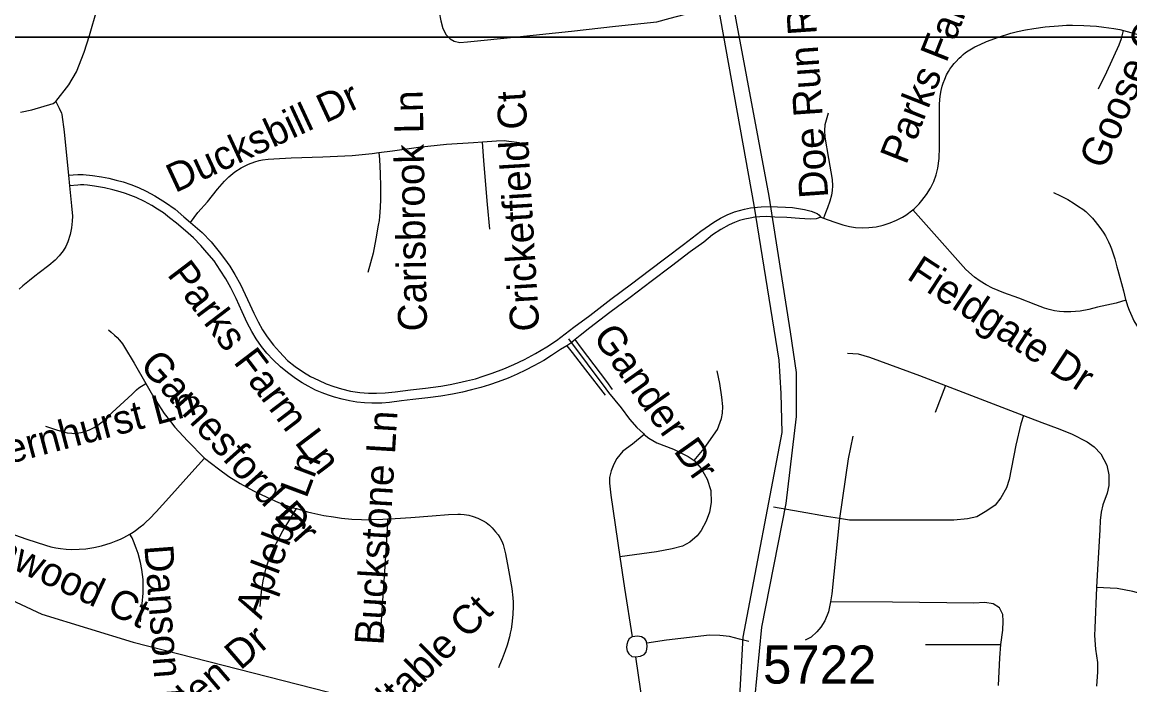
# Model space of a CAD drawing. Extents: x 1383679 to 1536984, y 460658 to 651027.
# Drawn here: x 1456433 to 1460069, y 475190 to 477365 of the extents above; entities that cross this region are included whole.
import ezdxf

# ---------------------------------------------------------------- set-up
doc = ezdxf.new("R2010")
doc.units = 0
for name, color, linetype in [('Exist Road Non-System Type 51', 7, 'Continuous'), ('Exist Road Non-System Type 51 Label', 7, 'Continuous'), ('Exist Road Secondary Type 51 Attributed', 7, 'Continuous'), ('Exist Road Secondary Type 51 Divided Attributed', 7, 'Continuous'), ('Exist Road Secondary Type 51 Number Label', 7, 'Continuous'), ('Exist Utilities Electrical Transmission Line', 7, 'Continuous'), ('Map Preparation Inset Cut Line', 7, 'Continuous')]:
    doc.layers.add(name, color=color, linetype=linetype)

msp = doc.modelspace()

# ---------------------------------------------------------------- linework, layer by layer
at = {"layer": 'Exist Road Non-System Type 51'}
for p, q in [((1456584.9, 476862.5), (1456588.5, 476827.7)), ((1459054.5, 476725.2), (1459063, 476722.4)), ((1459463.6, 476172.8), (1459429.6, 476083.9)), ((1459463.6, 476172.8), (1459720.1, 476074)), ((1459398, 475322.6), (1459645.4, 475323.2))]:
    msp.add_line(p, q, dxfattribs=at)
for points in [[(1457696.4, 477548.9), (1457721.9, 477541.8), (1457745.6, 477535.2), (1457767.6, 477524), (1457784.2, 477510.3), (1457792.6, 477496.1), (1457796.8, 477480.6), (1457798.5, 477452.7), (1457799.8, 477422.4), (1457801.5, 477397.4), (1457806.9, 477369.5), (1457813.4, 477344.6), (1457824.1, 477323.2), (1457837.8, 477310.1), (1457851.2, 477302.5), (1457869.2, 477298.8), (1457894.8, 477300.6), (1458057.6, 477317.2), (1458235.9, 477335.7), (1458380.1, 477352.2), (1458515.6, 477366.4), (1458559.6, 477378.7), (1458606.1, 477389.7), (1458624.4, 477398.2)], [(1459637.4, 477316), (1459678.3, 477328.6), (1459699.5, 477334.2), (1459725.7, 477339.6), (1459754, 477344.2), (1459790.9, 477349.2), (1459834.1, 477353.4), (1459861.3, 477354.8), (1459880.9, 477355.1), (1459917.3, 477354.5), (1459959.5, 477351.6), (1459983.5, 477349.1), (1460016.5, 477344.4), (1460035.4, 477341), (1460048.1, 477338)], [(1459966.3, 477146.8), (1459993, 477202), (1460033.9, 477290.6), (1460041.5, 477311.7), (1460048.1, 477338)], [(1460048.1, 477338), (1460147.2, 477310.3), (1460200.9, 477290.3), (1460427.4, 477206)], [(1459356.5, 476749.5), (1459362.2, 476753.9), (1459377.5, 476769.4), (1459385.9, 476779.8), (1459401.2, 476799.8), (1459414, 476820.8), (1459424.9, 476842), (1459433.2, 476863.8), (1459438.7, 476885.9), (1459442.9, 476918), (1459444.1, 476955.2), (1459444.3, 477026.3), (1459444.3, 477066), (1459444.3, 477093.6), (1459445, 477112.7), (1459446.9, 477129.2), (1459449.1, 477141.1), (1459452.6, 477154.5), (1459455.7, 477164.4), (1459460.9, 477177.9), (1459467.3, 477192.5), (1459473.3, 477203.1), (1459478.1, 477210.6), (1459484.3, 477219.4), (1459492.4, 477229.2), (1459497.1, 477234.9), (1459508.5, 477247.2), (1459514.7, 477252.9), (1459522, 477259), (1459529.3, 477265.2), (1459537.8, 477271.3), (1459548.6, 477277.8), (1459559.9, 477284.3), (1459577, 477292.3), (1459598.3, 477301.2), (1459637.4, 477316)], [(1456542.8, 477104.2), (1456554.3, 477082.8), (1456561.8, 477066), (1456563.1, 477062), (1456571, 477004.9), (1456579.4, 476916.4), (1456584.9, 476862.5)], [(1459078.2, 477066), (1459067.7, 477028.5), (1459066.4, 477009.7), (1459068, 476987.4), (1459079.7, 476917.3), (1459091.8, 476849.1), (1459092.9, 476827.9), (1459092, 476812.4), (1459089.1, 476797), (1459083.9, 476777.7), (1459076.6, 476756.3), (1459069.7, 476739.6), (1459063, 476722.4)], [(1457603.7, 476937), (1457648.8, 476943.1), (1457734, 476955), (1457825.3, 476964.2), (1457914.1, 476970.7), (1457944, 476972.7)], [(1457944, 476972.7), (1457990.1, 476975.6), (1458014.6, 476976.3), (1458029.8, 476975.1), (1458065.2, 476970.2)], [(1457968.1, 476685.7), (1457960.4, 476766.5), (1457948.7, 476909.9), (1457944, 476972.7)], [(1456985.6, 476707.2), (1457009.8, 476740.7), (1457041.3, 476776), (1457074.4, 476816.6), (1457097.2, 476843.1), (1457111, 476857.3), (1457131, 476873.7), (1457151.9, 476887.4), (1457175.5, 476898.9), (1457196, 476906.7), (1457210.4, 476910.7), (1457221.7, 476913.1), (1457240.3, 476915.8), (1457258.5, 476917), (1457315.9, 476919.5), (1457420.1, 476923.4), (1457516.1, 476928), (1457581.9, 476934), (1457603.7, 476937)], [(1457603.7, 476937), (1457605.7, 476914.8), (1457607.7, 476868), (1457609, 476824.8), (1457608.8, 476784.6), (1457608.2, 476756.6), (1457606, 476727.1), (1457604.5, 476714.7), (1457601.8, 476698.6), (1457593.8, 476654.2), (1457584.5, 476606.7), (1457567.5, 476543.4)], [(1456584.9, 476862.5), (1456615.6, 476865.2), (1456632.6, 476864.7), (1456663.3, 476862), (1456692.9, 476857.5), (1456717.6, 476853.2), (1456741.6, 476847.1), (1456764.1, 476841.1), (1456789.5, 476832.1), (1456814.4, 476822.5), (1456839.4, 476810.8), (1456868.8, 476795.4), (1456902.9, 476773.8), (1456935, 476751), (1456963.2, 476726.8), (1456985.6, 476707.2)], [(1456588.5, 476827.7), (1456595.1, 476762.9), (1456597.6, 476728), (1456597.2, 476712), (1456594.8, 476690.6), (1456590.4, 476668.2), (1456583.1, 476644.6), (1456575.6, 476628.5), (1456567.1, 476614.9), (1456554.7, 476598.6), (1456541.1, 476584.4), (1456520.7, 476566.1), (1456488.6, 476542.1), (1456474.4, 476531.5), (1456457.3, 476517.8), (1456435.5, 476499.8), (1456423.3, 476489.3)], [(1458220.5, 476303.3), (1458200.1, 476290.4), (1458170.7, 476270.7), (1458145.1, 476255.1), (1458112.5, 476237.6), (1458085.5, 476223.5), (1458057.8, 476210.1), (1458027.9, 476197.3), (1457995.5, 476185.3), (1457967.2, 476175.2), (1457938.1, 476166.2), (1457907.6, 476158.2), (1457877.8, 476150.7), (1457845, 476144.1), (1457807.4, 476137.7), (1457764.6, 476132.6), (1457715, 476126.8), (1457678.3, 476122.2), (1457638.6, 476116.7), (1457613.7, 476115), (1457580.8, 476114.4), (1457556.5, 476115.9), (1457530.8, 476118.6), (1457506.9, 476122.3), (1457483.2, 476127.4), (1457458.5, 476134.3), (1457438, 476140.8), (1457417.6, 476148.4), (1457396, 476158), (1457371.2, 476170.1), (1457351.5, 476181.6), (1457330, 476196.1), (1457303.6, 476215.3), (1457281.1, 476234.1), (1457256.8, 476257.5), (1457236.4, 476278.7), (1457218.6, 476300.5), (1457200.9, 476326.4), (1457186.8, 476350), (1457171.8, 476378.7), (1457155.4, 476414.4), (1457135.4, 476458.1), (1457117.9, 476492.8), (1457101.8, 476522.4), (1457083.1, 476551.7), (1457062.5, 476581.7), (1457039.3, 476609.3), (1457018.8, 476632.7), (1456995.2, 476657.5), (1456969.4, 476680.8), (1456939.2, 476706), (1456916.6, 476723.4), (1456896.3, 476738.9), (1456877.4, 476751.5), (1456858.6, 476763), (1456834.3, 476776.2), (1456806.7, 476789.4), (1456771.5, 476803.1), (1456754, 476808.7), (1456730.2, 476815.4), (1456702.8, 476821.6), (1456669.8, 476827.2), (1456647.2, 476829.8), (1456635.5, 476830.8), (1456624.8, 476831), (1456615.7, 476830.5), (1456588.5, 476827.7)], [(1459817.7, 476806.2), (1459840.6, 476795.2), (1459865.2, 476782.8), (1459886.1, 476770.3), (1459900.5, 476760.7), (1459914.1, 476751.4), (1459924, 476743.4), (1459933.1, 476735.3), (1459945.8, 476721.8), (1459955.2, 476711.2), (1459963, 476701.5), (1459973.7, 476687), (1459982.9, 476672.8), (1459988.8, 476663.4), (1459993.9, 476653.4), (1459998.9, 476644), (1460003.9, 476632.1), (1460008.5, 476620.8), (1460013, 476608.3), (1460019, 476588.4), (1460026.5, 476562.2), (1460029.8, 476550.9), (1460047.5, 476483.5), (1460054.8, 476455.2), (1460055.6, 476452.3)], [(1456985.6, 476707.2), (1457023.2, 476674.4), (1457053.3, 476644.2), (1457079.7, 476611.3), (1457097.4, 476588.6), (1457113.9, 476564.5), (1457131.1, 476537.5), (1457149.3, 476504.5), (1457165, 476471.6), (1457180.2, 476438.7), (1457193, 476410.2), (1457207.3, 476382.2), (1457221.7, 476355.9), (1457237.4, 476332.3), (1457257.3, 476305.3), (1457277.3, 476282.9), (1457304.2, 476255.1), (1457328.9, 476235.2), (1457356.3, 476216.5), (1457379.5, 476202.5), (1457405.1, 476189.8), (1457431, 476178.3), (1457455.8, 476169.4), (1457480.6, 476161.5), (1457510.1, 476154.7), (1457541.1, 476150.3), (1457570, 476148), (1457596.2, 476147.2), (1457623.8, 476148.5), (1457657.4, 476152.4), (1457707.9, 476158.6), (1457756.3, 476164.2), (1457807, 476171), (1457837.7, 476176.3), (1457863.3, 476181.2), (1457890.9, 476187.6), (1457920.5, 476195.1), (1457945.9, 476203), (1457975.6, 476213.2), (1458014.3, 476227.9), (1458046.5, 476241.4), (1458081.8, 476258.6), (1458118.2, 476278), (1458154.9, 476300.1), (1458186.2, 476320), (1458243.8, 476363.9), (1458296.1, 476402.3), (1458365.6, 476455.7), (1458432.4, 476506.4), (1458492.5, 476551.5), (1458545.5, 476591.3), (1458603.3, 476635.2), (1458660.7, 476678.9), (1458703.1, 476709.1), (1458724.7, 476722.3), (1458746.7, 476733.3), (1458771.3, 476743.1), (1458803.8, 476751.6), (1458823, 476755.4), (1458858.7, 476759.2), (1458889, 476759.9), (1458912.2, 476759), (1458938.8, 476758.1), (1458961.3, 476756.5), (1458981, 476753.9), (1459000.6, 476750.2), (1459022.7, 476744.4), (1459042.2, 476736.9), (1459048.3, 476732.7), (1459054.5, 476725.2)], [(1459063, 476722.4), (1459096.7, 476709.5), (1459126.2, 476700.1), (1459148.1, 476694.5), (1459167.7, 476691.4), (1459191.3, 476690.3), (1459211.9, 476691.4), (1459236.1, 476693.2), (1459258.7, 476698.7), (1459282.5, 476706.6), (1459303.3, 476715.8), (1459322.3, 476725.1), (1459333.1, 476731.8), (1459356.5, 476749.5)], [(1460055.6, 476452.3), (1460023.5, 476443.2), (1459962.9, 476429.3), (1459934.4, 476422.7), (1459905.5, 476416.9), (1459890.4, 476415.4), (1459875.3, 476414.2), (1459852.2, 476414.4), (1459837.3, 476415.4), (1459820.9, 476418), (1459803.9, 476421.8), (1459789, 476426.5), (1459760.4, 476437.2), (1459704.1, 476459), (1459654.9, 476477.4), (1459618, 476492.1), (1459597.3, 476502.7), (1459577, 476514.9), (1459558.6, 476527.9), (1459530.8, 476553.7), (1459417.4, 476680.4), (1459356.5, 476749.5)], [(1459054.5, 476725.2), (1459039, 476719.2), (1459019.6, 476718.6), (1458983.9, 476721.3), (1458942.6, 476724.1), (1458902.9, 476725.6), (1458875.1, 476727.4), (1458853.9, 476726.5), (1458837.3, 476724.8), (1458821.9, 476722.3), (1458804.9, 476718.4), (1458787.6, 476713.7), (1458770.6, 476707.5), (1458753.4, 476699.6), (1458725.8, 476684.6), (1458699.1, 476666.9), (1458669.8, 476643.6), (1458625.7, 476610.9), (1458564.3, 476564.8), (1458497.8, 476514), (1458428.6, 476461.7), (1458362.3, 476411.8), (1458295.9, 476361.9), (1458263.9, 476336.5), (1458247.9, 476323.4)], [(1460055.6, 476452.3), (1460060.9, 476434.2), (1460066.7, 476419.7), (1460074.8, 476400.6), (1460082.2, 476385.5), (1460090.5, 476370.8), (1460108.8, 476344.9), (1460128.3, 476322.7), (1460151, 476300.6), (1460179.1, 476279.1), (1460206.6, 476261.9), (1460237.1, 476248), (1460271.7, 476235), (1460320.8, 476221.1), (1460394.2, 476200.3), (1460437, 476190.9)], [(1456715.8, 476355.7), (1456725.3, 476348.3), (1456736.1, 476338.4), (1456744.8, 476330.1), (1456752.6, 476321.3), (1456761.7, 476309.9), (1456769, 476298.8), (1456800.7, 476246), (1456838.6, 476179.7)], [(1458247.9, 476323.4), (1458233.6, 476311.6), (1458220.5, 476303.3)], [(1458226.5, 476325.8), (1458348.4, 476161.9), (1458357.4, 476149.8), (1458398.5, 476100), (1458426.2, 476062.7), (1458450.4, 476034.9), (1458472.1, 476015.6), (1458474.6, 476011.5)], [(1458370.6, 476160.2), (1458351.5, 476185.4), (1458269.2, 476294.8), (1458247.9, 476323.4)], [(1458220.5, 476303.3), (1458237.9, 476281.1), (1458282, 476223.8), (1458346.1, 476140.9)], [(1459142.1, 476279.2), (1459176.9, 476276.7), (1459214.6, 476266.3), (1459378.2, 476205.5), (1459463.6, 476172.8)], [(1458639.1, 475927.2), (1458671, 475965.9), (1458715.6, 476028.9), (1458728.2, 476064.1), (1458731.8, 476081.6), (1458732.9, 476103.8), (1458729.4, 476134.2), (1458722.9, 476179.7), (1458714.5, 476220.7)], [(1456509.2, 476039.7), (1456548.7, 476026.3), (1456568.4, 476020.3), (1456581, 476017.8), (1456596.2, 476015.9), (1456601.6, 476015.6), (1456609.4, 476015.9), (1456618.7, 476017.3), (1456626.6, 476018.9), (1456638.4, 476022.2), (1456653.3, 476027.3), (1456662.2, 476031.3), (1456669.2, 476035), (1456681.4, 476042.6), (1456691.4, 476050.2), (1456698.2, 476055.9), (1456728.1, 476084), (1456793.5, 476144.6), (1456808.2, 476158.2), (1456816.2, 476164.6), (1456838.6, 476179.7)], [(1456838.6, 476179.7), (1456860.8, 476140.8), (1456878.8, 476111.3), (1456898.8, 476081.4), (1456919.2, 476054.8), (1456934.3, 476036.3), (1456976, 475990.7), (1457031.7, 475934.3)], [(1459720.1, 476074), (1459710.6, 476046.6), (1459694.6, 475976.7), (1459672.9, 475864.2), (1459663.4, 475836.8), (1459645.5, 475804.7), (1459626.6, 475780.1), (1459599.1, 475761.2), (1459566.1, 475742.3), (1459535.9, 475734.8), (1459490.5, 475730.9), (1459190, 475730.9), (1459148.4, 475730.9), (1459116.1, 475736.6)], [(1459720.1, 476074), (1459779.5, 476051.4), (1459830.6, 476032.5), (1459877.4, 476013.8), (1459928.9, 475988.1), (1459951.1, 475971.8), (1459973.4, 475948.3), (1459993, 475911.2), (1459999.2, 475879.8), (1459999.2, 475845), (1459994.8, 475820), (1459980.5, 475781.6), (1459975.1, 475757.5), (1459971.5, 475729.8), (1459970.6, 475699.4), (1459960.9, 475550.2), (1459959.1, 475509.8)], [(1458474.6, 476011.5), (1458435.9, 475980.7), (1458404.6, 475957.8), (1458385.2, 475933.6), (1458374.4, 475914.3), (1458365.9, 475892.6), (1458361.1, 475870.9), (1458361.1, 475852.8), (1458364.8, 475813), (1458394.4, 475610.1)], [(1458474.6, 476011.5), (1458489.8, 475999.8), (1458516.6, 475984.6), (1458570.4, 475963.5), (1458618.4, 475940.2), (1458639.1, 475927.2)], [(1459159.6, 476006.8), (1459144.2, 475932.2), (1459116.1, 475736.6)], [(1456786.3, 475685), (1456786.5, 475685.1), (1456796.6, 475691.4), (1456804.6, 475697), (1456820.2, 475708.7), (1456831.8, 475718.1), (1456840.3, 475725.4), (1456850.5, 475735.2), (1456872.9, 475758), (1456914.7, 475804.2), (1456990.2, 475888.6), (1457031.7, 475934.3)], [(1457031.7, 475934.3), (1457077.1, 475899.1), (1457111.5, 475874.6), (1457148.6, 475851.2), (1457191.7, 475827.5), (1457235.6, 475805.9), (1457274.6, 475789.1), (1457318.1, 475772.8), (1457332.8, 475768.7)], [(1458639.1, 475927.2), (1458661.6, 475900.4), (1458681.5, 475865.3), (1458693.1, 475827.9), (1458694.4, 475789.3), (1458688.5, 475756.6), (1458678, 475727.4), (1458661.6, 475697), (1458648.1, 475679.2), (1458624.1, 475658.7), (1458599.9, 475645.3), (1458566.1, 475636.9), (1458515.5, 475627.2), (1458394.4, 475610.1)], [(1457213.5, 475448.1), (1457218.1, 475496), (1457223.9, 475532.2), (1457234, 475574), (1457241.7, 475597.3), (1457248.6, 475616.4), (1457258.8, 475638.5), (1457267.4, 475657), (1457288.8, 475696), (1457310.4, 475730.4), (1457332.8, 475768.7)], [(1457332.8, 475768.7), (1457369.1, 475758.7), (1457383.8, 475755), (1457422.9, 475746.6), (1457454.2, 475741.3), (1457480.5, 475737.8), (1457514.4, 475734.6), (1457546.5, 475732.9), (1457571.8, 475732.5), (1457578.1, 475732.7), (1457616.5, 475733.8), (1457632.9, 475734.8)], [(1459116.1, 475736.6), (1459072.8, 475743.2), (1458986.8, 475758.3), (1458899.4, 475773.4)], [(1456235.7, 475756.1), (1456261.9, 475741.2), (1456304.2, 475722.1), (1456367.1, 475697.5), (1456448.1, 475668.7), (1456509.6, 475648.3), (1456527.1, 475643.6), (1456543.8, 475639.9), (1456558.8, 475637.6), (1456577.5, 475635.6), (1456594.4, 475634.9), (1456620.2, 475635.5), (1456642.3, 475636.9), (1456668.1, 475641.1), (1456693.7, 475646.8), (1456725.2, 475656.5), (1456741.4, 475662.8), (1456755.3, 475668.9), (1456766.8, 475674.1), (1456776.2, 475679.2), (1456786.3, 475685)], [(1457609, 475348.2), (1457613.7, 475417.5), (1457624, 475578.4), (1457632.6, 475719.2), (1457632.9, 475734.8)], [(1457632.9, 475734.8), (1457657.4, 475736.2), (1457708.7, 475739.9), (1457778.4, 475745.2), (1457832.2, 475749), (1457863.1, 475750.8), (1457871.7, 475750.7), (1457883.4, 475749.9), (1457898.8, 475747.4), (1457913.4, 475743.2), (1457928.2, 475737.7), (1457946.3, 475729.1), (1457955.5, 475723.4), (1457966.9, 475714.8), (1457975.8, 475705.8), (1457986.7, 475693.1), (1457994.8, 475682.8), (1458001.2, 475673.5), (1458006.8, 475662.4), (1458011.6, 475650.8), (1458015.2, 475638.4), (1458019.6, 475620.1), (1458028.4, 475573.5), (1458039.7, 475506.9), (1458043.6, 475475.5), (1458044.3, 475461.6), (1458044.7, 475449.2), (1458043.4, 475421.4), (1458039.9, 475389.9), (1458037.6, 475373.4), (1458035.1, 475359.6), (1458032.3, 475348.3), (1458024.8, 475321), (1458018.2, 475302.4), (1458008.2, 475275.7), (1457999.9, 475255.1), (1457995.9, 475246)], [(1459116.1, 475736.6), (1459090.5, 475489), (1459085.6, 475462.7)], [(1456821.7, 475397.6), (1456827, 475455.9), (1456829.7, 475491), (1456830.3, 475516.1), (1456829.7, 475536.6), (1456828.2, 475552.5), (1456825.7, 475569.3), (1456821.1, 475592.2), (1456813.2, 475621.2), (1456807.4, 475639.3), (1456798.4, 475662.5), (1456793.7, 475672.7), (1456786.3, 475685)], [(1458394.4, 475610.1), (1458409.4, 475507.9), (1458435.6, 475348.2)], [(1459959.1, 475509.8), (1459953.6, 475376), (1459952.8, 475351.9), (1459956.4, 475308.1), (1459962.6, 475264.3), (1459962.6, 475233.1), (1459959.2, 475186.1)], [(1460624.9, 475267.2), (1460612.4, 475284.3), (1460577.6, 475329.1), (1460539.4, 475358.9), (1460503, 475378.8), (1460428.4, 475400.4), (1460078.6, 475496.6), (1460027.1, 475506.5), (1459959.1, 475509.8)], [(1459085.6, 475462.7), (1459080, 475429.8), (1459067, 475400.7), (1459054, 475380.2)], [(1459645.4, 475323.2), (1459652.2, 475369.7), (1459653.4, 475399.4), (1459652.2, 475421.2), (1459640.4, 475443.5), (1459620.6, 475455.8), (1459592.6, 475460.2), (1459556.8, 475459), (1459289.6, 475461.4), (1459085.6, 475462.7)], [(1459054, 475380.2), (1459041.6, 475364.8), (1459022.4, 475347.4), (1459003.1, 475336.8)], [(1458435.6, 475348.2), (1458425, 475341.9), (1458420.4, 475333.3), (1458417.6, 475323), (1458416.9, 475312.6), (1458418.6, 475300.8), (1458423.9, 475291.8), (1458434.1, 475284), (1458445.6, 475282.5)], [(1458483, 475327.2), (1458480.6, 475335.4), (1458476.9, 475341.8), (1458465.8, 475347.8), (1458452.1, 475349.8), (1458435.6, 475348.2)], [(1458818.1, 475333.2), (1458787.9, 475340.5), (1458754.1, 475348.9), (1458722.6, 475352.6), (1458688.8, 475353.8), (1458548.1, 475336.7), (1458483, 475327.2)], [(1458445.6, 475282.5), (1458462.4, 475284.5), (1458474.1, 475290.3), (1458480.6, 475297.9), (1458483, 475307.3), (1458483.8, 475316.9), (1458483, 475327.2)], [(1459637.9, 475188.2), (1459642.2, 475278.6), (1459645.4, 475323.2)], [(1458445.6, 475282.5), (1458469.6, 475117.2), (1458485.1, 475018.3)]]:
    msp.add_lwpolyline(points, dxfattribs=at)
at = {"layer": 'Exist Road Secondary Type 51 Attributed'}
msp.add_lwpolyline([(1456427.3, 477070.2), (1456464.2, 477077), (1456534.3, 477098.6), (1456542.8, 477104.2), (1456585.7, 477158.9), (1456611.4, 477202.6), (1456636.6, 477266.2), (1456653.7, 477321), (1456829.7, 477934.5), (1456869, 478083.4), (1456883.3, 478148.5), (1456909.6, 478279.4), (1456951.5, 478498.5), (1457079.3, 479143.2), (1457091.1, 479196.8), (1457099.8, 479243.5), (1457101.4, 479259), (1457091.2, 479364.1), (1457067.4, 479430.8), (1456494.2, 480699.2)], dxfattribs=at)
at = {"layer": 'Exist Road Secondary Type 51 Divided Attributed'}
for points in [[(1458837.8, 475143.5), (1458860.6, 475380), (1458940.2, 475785.1), (1458975, 476071.6), (1458974.4, 476215.4), (1458954.5, 476349.3), (1458884.4, 476793.7), (1458630.1, 478157.4), (1458544.7, 478502.2), (1458470.7, 478670.4), (1458422.3, 478781.5), (1458271.4, 479018.1), (1458100.5, 479226.1), (1457884.5, 479508.8), (1457764.8, 479708.1), (1457688, 479902.1), (1457668.3, 480076.8), (1457671.2, 480649.6), (1457683.3, 481012.4)], [(1457618.7, 480994.9), (1457614.2, 480886.1), (1457614.2, 480629.6), (1457614, 480244), (1457625.4, 479987.5), (1457645.3, 479865), (1457717.2, 479668.5), (1457799.1, 479528.7), (1457995.2, 479271.7), (1458223, 478995.3), (1458353.9, 478807.2), (1458442.2, 478630.5), (1458527.6, 478391.1), (1458613.1, 477994.2), (1458834.8, 476764.4), (1458916.6, 476255.7), (1458923.1, 476147), (1458926, 476018.8), (1458798.2, 475346.4), (1458786.6, 475132.1)]]:
    msp.add_lwpolyline(points, dxfattribs=at)
at = {"layer": 'Exist Utilities Electrical Transmission Line'}
msp.add_lwpolyline([(1453014.9, 477138.1), (1453821.9, 476745.3), (1454321.7, 476494.2), (1454964, 476178.3), (1455473.7, 475920.9), (1455981.2, 475667.6), (1456308.6, 475509.6), (1456496.9, 475421.9), (1456797.4, 475330.4), (1457486.6, 475153.9), (1458281.1, 474943.2), (1458957.9, 474758.9), (1459627.2, 474588.6), (1460274, 474406.7), (1460927.2, 474230.7), (1461607.9, 474042.3), (1462317, 473863.2)], dxfattribs=at)
at = {"layer": 'Map Preparation Inset Cut Line'}
for points in [[(1446195.4, 477316), (1480703, 477316), (1498974.3, 494868.2), (1521133.6, 516155.5), (1521133.6, 520758.2), (1458567.8, 520758.2), (1458567.8, 493672.2), (1446195.4, 493672.2), (1446195.4, 477316)], [(1437474.3, 477316), (1437474.3, 461213.3), (1475802.8, 461213.3), (1475802.8, 477316), (1437474.3, 477316)]]:
    msp.add_lwpolyline(points, dxfattribs=at)

# ---------------------------------------------------------------- texts
at = {"layer": 'Exist Road Non-System Type 51 Label'}
for s, rotation, p in [('Parks Farm Ln', 68.4908, (1459334.2, 476893.9)), ('Doe Run Rd', 94.0064, (1459079.2, 476790.1)), ('Goose Ct', 66.8976, (1459986.5, 476878.4)), ('Ducksbill Dr', 24.8776, (1456934.7, 476803.7)), ('Carisbrook Ln', 91.0627, (1457762.1, 476351.1)), ('Cricketfield Ct', 93.4121, (1458130.9, 476352.9)), ('Parks Farm Ln', 307.2228, (1456906.2, 476536.6)), ('Fieldgate Dr', 326.7355, (1459332.7, 476524.9)), ('Gander Dr', 305.3645, (1458303.2, 476332.6)), ('Gamesford Dr', 311.7076, (1456815.1, 476237)), ('Fernhurst Ln', 14.8392, (1456313.8, 475894.8)), ('Buckstone Ln', 86.5463, (1457618.5, 475319)), ('Apleby Ln', 69.4967, (1457217.3, 475402.6)), ('Charnwood Ct', 335.037, (1456084.8, 475717.4)), ('Danson Dr', 274.338, (1456833.5, 475646.9)), ('Roundtable Ct', 44.9373, (1457408.8, 474854.3)), ('Mitchell Glen Dr', 40.7808, (1456566.5, 474733.5))]:
    msp.add_text(s, height=95, rotation=rotation, dxfattribs=at).set_placement(p)
at = {"layer": 'Exist Road Secondary Type 51 Number Label'}
msp.add_text('5722', height=125, dxfattribs=at).set_placement((1458864.7, 475194.6))

doc.saveas('drawing.dxf')
